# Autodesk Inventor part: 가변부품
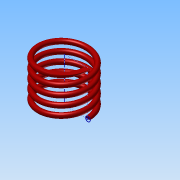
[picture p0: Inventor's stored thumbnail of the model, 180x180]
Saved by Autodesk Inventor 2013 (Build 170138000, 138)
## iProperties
Created: 2019-01
Part Number: 가변부품
Material: 스테인리스강
Document SubType Name: Modeling
Designer: Administrator
Density: 8.08 g/cm^3
Mass: 7.83149 g
Surface Area: 19.6313 cm^2
Volume: 0.969244 cm^3
Author: Administrator
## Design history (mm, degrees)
sketch "스케치2"
  geometry: L1 (0, 0)-(10, 0); L2 (10, 0)-(10, 18.7); L3 (10, 18.7)-(0, 18.7); L4 (0, 18.7)-(0, 0); C1 r 1 at (10, 0)
  constraints: 8 end point, 2 parallel, 1 centre point, 1 coincident, 1 horizontal, 1 perpendicular
  dimensions: "d0" = 20 diameter of L2 L4; "d2" = 18.7 distance of L1.end L2.end (derived); "d3" = 2 diameter of C1
feature "코일1" sketch "스케치2" pitch "d4" = 10; turns "d6" = 5; dims "d5" = 18.7 (= d2), "d7" = 0, angle "d8" = 90 deg, angle "d9" = 90 deg, "d10" = 0, "d11" = 0
node "작업 평면1"
feature "분할1"
feature "분할2"
node "솔리드1"
